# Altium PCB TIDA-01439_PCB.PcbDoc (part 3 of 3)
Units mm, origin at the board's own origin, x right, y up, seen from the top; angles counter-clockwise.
Board outline 105.8 x 40.5 mm, 4 copper layers (Layer 1 - Top Layer, Layer 2 - GND, Layer 3 - POWER, Layer 4 - Bottom Layer), stack 1.56 mm thick; 145 components, 123 nets, 523 pads, 227 vias.
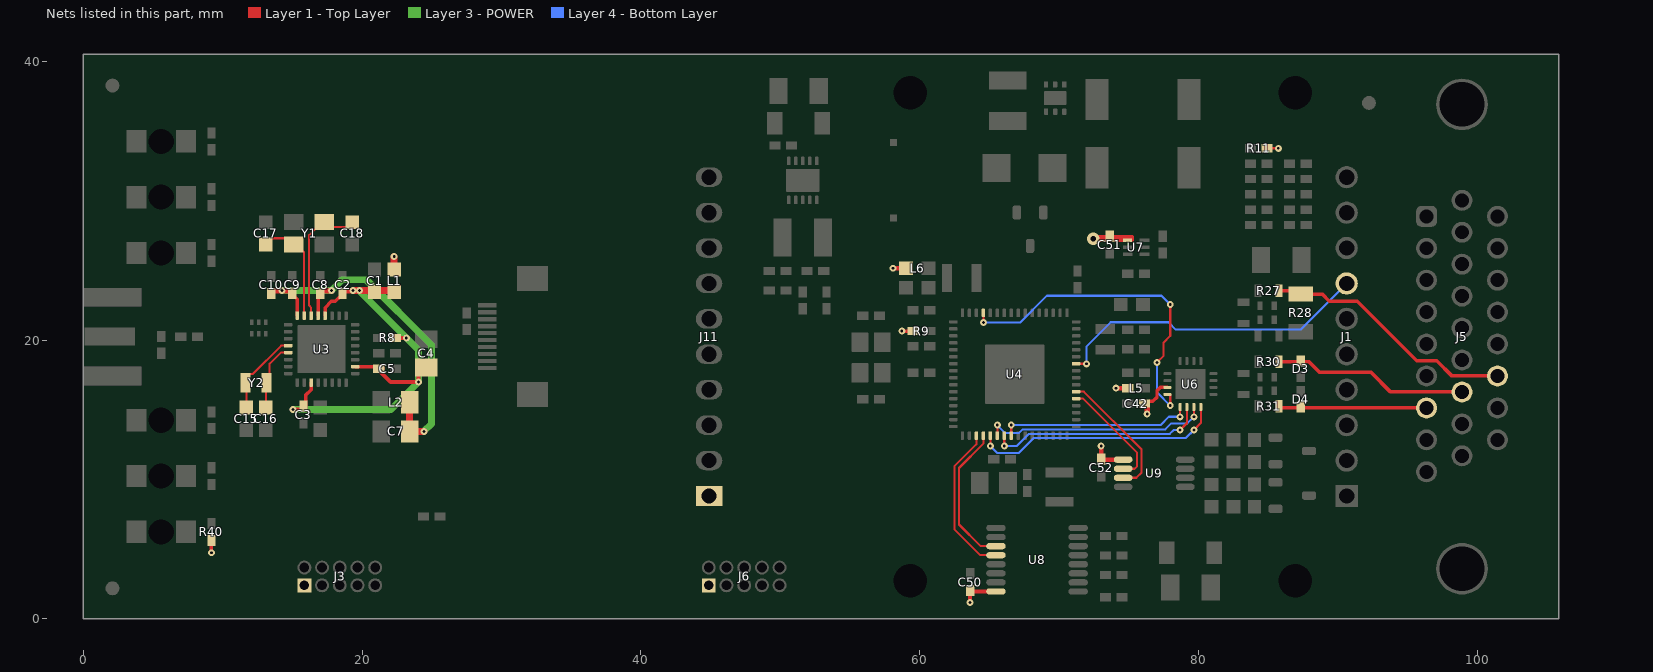
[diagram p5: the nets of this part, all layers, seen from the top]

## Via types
v1: diameter 0.5, hole 0.2, Layer 1 - Top Layer to Layer 4 - Bottom Layer, 215 vias
v2: diameter 0.9, hole 0.4, Layer 1 - Top Layer to Layer 4 - Bottom Layer, 12 vias

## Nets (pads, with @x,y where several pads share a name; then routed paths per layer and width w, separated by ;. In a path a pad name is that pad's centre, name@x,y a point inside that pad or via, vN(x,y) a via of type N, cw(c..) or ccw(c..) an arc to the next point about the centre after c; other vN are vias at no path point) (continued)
RTD1: J5.24 R27.1 R28.2 | length 18.7
  Layer 1 - Top Layer w0.25: R27.1@85.762,23.55 R28.2@87.9,23.55 ; R28.2@87.3,23.3 88.85,23.3 89.36,22.79 91.37,22.79 95.635,18.525 97.05,18.525 98.15,17.425 J5.24@101.41,17.425
RTD2: D3.1 J5.16 R30.1 | length 14
  Layer 1 - Top Layer w0.25: R30.1@85.762,18.45 87.9,18.45 88.64,17.71 92.315,17.71 93.745,16.28 J5.16@98.87,16.28
RTD3: D4.1 J5.7 R31.1 | length 10.6
  Layer 1 - Top Layer w0.25: R31.1@85.762,15.25 85.877,15.135 J5.7@96.33,15.135
RTD_CLK: U4.6 U6.15 | length 16.3
  Layer 1 - Top Layer w0.15: U4.6@65.55,13.15 v1(65.55,13.9) ; v1(79.65,14.5) U6.15@79.65,15.2
  Layer 4 - Bottom Layer w0.15: v1(65.55,13.9) 66.125,13.325 67.1,13.325 67.375,13.6 77.6,13.6 78.025,14.025 79.175,14.025 v1(79.65,14.5)
RTD_DRDY: U4.45 U6.12 | length 24.2
  Layer 1 - Top Layer w0.15: v1(64.55,21.25) U4.45@64.55,21.95 ; v1(77,18.4) 77.475,18.875 77.475,19.825 77.95,20.3 v1(77.95,22.55) ; U6.12@77.75,16.1 77.95,16.1 v1(77.95,15.3)
  Layer 4 - Bottom Layer w0.15: v1(64.55,21.25) 67.175,21.25 69.1,23.175 77.325,23.175 v1(77.95,22.55) ; v1(77,18.4) 77,16.25 v1(77.95,15.3)
RTD_NCS: U4.5 U6.16 | length 18.1
  Layer 1 - Top Layer w0.15: v1(65.05,12.4) U4.5@65.05,13.15 ; v1(79.65,13.55) 80.15,14.05 U6.16@80.15,15.2
  Layer 4 - Bottom Layer w0.15: v1(65.05,12.4) 65.55,11.9 67.075,11.9 68.15,12.975 79.075,12.975 v1(79.65,13.55)
RTD_SIMO: U4.7 U6.14 | length 15.7
  Layer 1 - Top Layer w0.15: v1(66.05,12.4) U4.7@66.05,13.15 ; v1(78.65,13.55) 79.15,14.05 U6.14@79.15,15.2
  Layer 4 - Bottom Layer w0.15: v1(66.05,12.4) 66.95,12.4 67.825,13.275 77.925,13.275 78.2,13.55 v1(78.65,13.55)
RTD_SOMI: U4.8 U6.13 | length 13.8
  Layer 1 - Top Layer w0.15: U4.8@66.55,13.15 v1(66.55,13.9) ; v1(78.65,14.5) U6.13@78.65,15.2
  Layer 4 - Bottom Layer w0.15: v1(66.55,13.9) 77.25,13.9 77.85,14.5 v1(78.65,14.5)
SOMI: J1.7 U4.26 | length 23
  Layer 1 - Top Layer w0.15: U4.26@71.2,18.3 v1(71.95,18.3)
  Layer 4 - Bottom Layer w0.15: v1(71.95,18.3) 71.95,19.55 73.675,21.275 77.825,21.275 78.35,20.75 87.29,20.75 J1.7@90.6,24.06
UART_A0_RX: U4.3 U8.12 | length 11.3
  Layer 1 - Top Layer w0.15: U4.3@64.05,13.15 64.05,12.525 62.475,10.95 62.475,6.425 64.325,4.575 U8.12@65.45,4.575 U8.12@65.65,4.575
UART_A0_TX: U4.4 U8.11 | length 10.6
  Layer 1 - Top Layer w0.15: U4.4@64.55,13.15 64.55,12.575 62.8,10.825 62.8,6.775 64.35,5.225 U8.11@65.45,5.225 U8.11@65.65,5.225
UART_A2_RX: U4.21 U9.2 | length 8
  Layer 1 - Top Layer w0.15: U4.21@71.2,15.8 71.7,15.8 75.575,11.925 75.575,10.95 75.4,10.775 U9.2@74.575,10.775
UART_A2_TX: U4.22 U9.3 | length 9.5
  Layer 1 - Top Layer w0.15: U4.22@71.2,16.3 71.75,16.3 75.9,12.15 75.9,10.5 75.525,10.125 U9.3@74.575,10.125
VCC: C42.1 C50.1 C51.1 C52.1 J3.1 J6.1 J11.1 L1.2 L5.1 L6.2 R9.2 R11.2 R40.1 U6.11 U7.1 U8.16 U9.1 | length 18.8
  Layer 1 - Top Layer w0.2: R11.2@84.9,33.75 v1(85.7,33.75)
  Layer 1 - Top Layer w0.25: v1(9.2,4.75) R40.1@9.2,5.65 ; v1(58.7,20.65) R9.2@59.525,20.65 ; C51.1@73.6,27.4 73.65,27.4 75.225,27.4 75.225,27.15 U7.1@74.88,27.15 ; C42.1@76.3,15.425 76.475,15.6 76.7,15.6 77,15.9 77,16.375 77.225,16.6 U6.11@77.75,16.6
  Layer 1 - Top Layer w0.3: v1(58.075,25.15) L6.2@59,25.15 ; v1(63.6,1.175) C50.1@63.6,1.975 ; C50.1@63.6,2.05 C50.1@63.6,1.975 ; U8.16@65.45,1.975 C50.1@63.6,1.975 ; C52.1@73,11.225 C52.1@73,11.425 ; v1(73,12.4) C52.1@73,11.45 C52.1@73,11.425 ; v1(74.05,16.55) L5.1@74.9,16.55 ; U9.1@74.575,11.425 C52.1@73,11.425
  Layer 1 - Top Layer w0.4: v1(76.3,14.7) C42.1@76.3,15.425
  Layer 1 - Top Layer w0.5: L1.2@22.3,25.05 v1(22.3,26) ; v2(72.425,27.275) C51.1@73.775,27.275 ; C51.1@73.6,27.45 73.65,27.4 C51.1@73.775,27.275 ; 75.1,27.275 74.9,27.275 C51.1@73.775,27.275
VDDR: C7.1 C8.1 C9.1 C10.1 L2.2 U3.29 U3.32 | length 29.1
  Layer 1 - Top Layer w0.25: C10.1@13.5,23.35 C10.1@13.5,23.6 ; C9.1@14.825,23.15 15.125,23.15 15.35,22.925 U3.32@15.35,21.75 ; C9.1@15,23.35 15,23.55 C9.1@15,23.6 ; U3.29@16.85,21.75 C8.1@16.85,23.6
  Layer 1 - Top Layer w0.4: C10.1@13.5,23.55 v1(14.25,23.55) C9.1@15,23.55 ; C8.1@16.9,23.55 v1(17.8,23.55)
  Layer 1 - Top Layer w0.5: C7.1@23.416,13.75 23.716,13.45 v1(24.45,13.45) ; C7.1@23.416,13.85 L2.2@23.416,15.85
  Layer 3 - POWER w0.5: v1(14.25,23.55) v1(17.8,23.55) 18.575,24.325 20.3,24.325 24.975,19.65 24.975,13.995 24.45,13.47 v1(24.45,13.45)
VDDS: C1.1 C2.1 C3.1 C4.1 C5.1 L1.1 R8.2 U3.11 U3.18 U3.28 | length 35.6
  Layer 1 - Top Layer w0.254: v1(15.05,15.025) 15.975,15.025 15.975,16.075 16.35,16.45 U3.11@16.35,16.95 ; U3.28@17.35,21.75 17.35,22.325 17.8,22.775 18.075,22.775 C2.1@18.425,23.125 ; U3.18@19.5,18.1 21.475,18.1 21.475,17.575
  Layer 1 - Top Layer w0.3: C5.1@21.2,17.95 21.2,17.85 21.475,17.575 22.05,17 v1(24.05,17) 24.05,17.684 C4.1@24.6,18.234 ; R8.2@22.4,20.15 v1(23.175,20.15)
  Layer 1 - Top Layer w0.4: C2.1@18.625,23.55 v1@19.375,23.55
  Layer 1 - Top Layer w0.5: v1@19.375,23.55 22.3,23.55 L1.1@22.3,23.45 ; C4.1@24.6,18.234 C4.1@24.766,18.4
  Layer 3 - POWER w0.5: v1(15.05,15.025) 22.075,15.025 v1(24.05,17) 24.05,19.275 v1(23.175,20.15) 19.775,23.55 v1@19.375,23.55
  other v1: 19.35,23.55 19.825,23.55
X24M_N: C18.1 U3.30 Y1.1 | length 9.3
  Layer 1 - Top Layer w0.15: U3.30@16.35,21.75 16.35,22.325 16.2,22.475 16.2,27.525 16.775,28.1 C18.1@19.375,28.1
X24M_P: C17.1 U3.31 Y1.3 | length 7.8
  Layer 1 - Top Layer w0.15: C17.1@13.2,26.9 13.6,27.3 14.825,27.3 15.85,26.275 U3.31@15.85,21.75
X32K_Q1: C15.2 U3.4 Y2.1 | length 6.3
  Layer 1 - Top Layer w0.15: C15.2@11.7,15.15 11.7,17.575 12.175,17.575 14.2,19.6 U3.4@14.7,19.6
X32K_Q2: C16.1 U3.5 Y2.2 | length 5.1
  Layer 1 - Top Layer w0.15: C16.1@13.1,15.15 13.1,16.975 13.375,16.975 13.375,18.3 14.175,19.1 U3.5@14.7,19.1
pads on no net: D1.0 D2.0 D8.0 D9.0 D10.0 D13.0 FID1.1 FID2.1 FID3.1 J3.6 J3.7 J3.8 J4.M1 J4.M2 J5.6 J5.15 J5.23 J6.6 J6.7 J6.8 U1.7@69.25,37.35 U1.7@70.15,37.35 U3. U3.3 U3.6 U3.7 U3.10 U3.15 U3.20 U3.21 U3.22 U3.27 U4.37 U4.46 U4.61 U4.62 U4.65@65.41,16.16 U4.65@65.41,17.55 U4.65@65.41,18.94 U4.65@66.8,16.16 U4.65@66.8,17.55 U4.65@66.8,18.94 U4.65@68.19,16.16 U4.65@68.19,17.55 U4.65@68.19,18.94 U5.6 U7.5 U8.7 U8.8 U8.9 U8.10

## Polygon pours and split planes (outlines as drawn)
GND on Layer 2 - GND "LAYER_2_-_GND_GND_P000" (solid, remove dead copper, pour order 0): 0.5,0.5 0.5,40 3.35,40 105.3,40 105.3,0.5
GND on Layer 1 - Top Layer "PolyDirectConnect" (solid, remove dead copper, pour order 4): 67.3,13.75 63.2,13.75 63,13.95 63,21.15 63.2,21.35 70.4,21.35 70.6,21.15 70.6,13.95 70.4,13.75
GND on Layer 1 - Top Layer "PolyDirectConnect" (solid, remove dead copper, pour order 8): 4.125,23.75 12.55,23.75 12.7,23.6 12.7,19.125 11.825,18.25 10.95,18.25 9.45,16.75 4.05,16.75 4.05,23.75
VCC on Layer 3 - POWER "LAYER_3_-_POWER_VCC_P002" (solid, remove dead copper, pour order 2): 1.6,1.25 1.6,34 1.6,38.9 48.1,38.9 53,34 95.25,34 98.1,31.15 98.1,21.75 98.6,21.25 104.55,21.25 104.55,1.25 95.25,1.25

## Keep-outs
Layer 1 - Top Layer:
  circle w0.1: c59.3,2.75 r2.5
  circle w0.1: c86.9,2.75 r2.5
  circle w0.1: c86.9,37.75 r2.5
  circle w0.1: c59.3,37.75 r2.5
Layer 2 - GND:
  lines w0.05: 11.8,12.325 13.75,12.325 14.05,12.625 14.05,18.375 14.4,18.725 14.95,18.725 ; 11.825,12.325 11.05,12.325 10.75,12.625 10.75,17.75 11.05,18.05 11.925,18.05 12.025,18.15 13.875,20 14.95,20 ; 15.45,22.05 15.45,25.5 15.075,25.875 12.35,25.875 12.15,26.075 12.15,29.175 12.4,29.425 20,29.425 20.25,29.175 20.25,26.2 19.925,25.875 16.925,25.875 16.55,25.5 16.55,22.05 ; 61.225,19.025 61.15,19.1 58.5,19.1 58.25,19.35 58.25,22.275 58,22.525 54.8,22.525 54.55,22.275 54.55,15.3 54.875,14.975 57.925,14.975 58.25,15.3 58.25,17.85 58.5,18.1 61.825,18.1 61.875,18.05 62.6,18.05 ; 70.875,20.3 71.725,20.3 72.95,21.525 77.45,21.525 77.45,18.875 76.8,18.875 76.5,18.575 73.35,18.575 73.125,18.8 70.9,18.8
Layer 4 - Bottom Layer:
  circle w0.1: c59.3,37.75 r2.5
  circle w0.1: c86.9,37.75 r2.5
  circle w0.1: c86.9,2.75 r2.5
  circle w0.1: c59.3,2.75 r2.5
Keep-Out Layer:
  lines w0.7: -0.5,16.35 -0.5,24.15 0,24.65 0,40.5 105.8,40.5 105.8,0 0,0 0,15.85 -0.5,16.35 ; 38.9,15.25 ccw(c39.9,15.25) 39.9,14.25 40.9,14.25 ccw(c40.9,15.25) 41.9,15.25 41.9,25.25 ccw(c40.9,25.25) 40.9,26.25 39.9,26.25 ccw(c39.9,25.25) 38.9,25.25 38.9,20.25 38.9,15.25
  text ".Layer_Name" at -13.844,-39.756 h1.52

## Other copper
Layer 1 - Top Layer:
  rectangle: 29.65,8.1 35.3,13.75
  region net GND: 49.7,23.15 49.7,25.5 50.1,25.9 50.9,25.9 50.9,28.85 50.225,29.525 50.225,30.475 50.375,30.625 53.725,30.625 53.725,32.275 50.15,32.275 50,32.425 50,34.25 50.6,34.85 50.6,38.875 47.6,38.875 47.6,23.15
  region net NetC26_1: 51.975,32.55 51.975,33.275 51.75,33.5 51.75,38.875 53.65,38.875 53.65,36.375 53.65,34.675 52.225,33.25 52.225,32.55
  region net NetL7_1: 52.475,32.55 52.475,33.125 54.375,35.025 61.05,35.025 61.25,34.825 61.25,33.9 56.113,33.9 56.113,32.4 54.95,32.4 54.8,32.55
  region net NetC27_1: 52.3,25.9 52.3,28.8 54.6,28.8 54.975,29.175 61.25,29.175 61.25,27.45 61.05,27.25 53.8,27.25 53.8,26.8 54.5,26.8 54.5,25.9
  region net NetFL1_1: 12.205,20.665 11.65,20.665 11.65,20.25 12.205,20.25
  region net GND: 68.9,37.675 68.9,36.1 68.8,36 65.225,36 65.225,35.15 70,35.15 70.5,35.65 70.5,37.675
  text ".Layer_Name" at -13.844,-39.756 h1.52
Layer 4 - Bottom Layer:
  text "GCD_13112" at 8.2,0.9 h0.9
  text ".Layer_Name" at -13.844,-39.756 h1.52

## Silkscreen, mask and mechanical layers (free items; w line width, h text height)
Top Overlay:
  region: 46.12,39.54 38.5,39.54 38.5,37 46.12,37
  lines w0.1: 61.3,19.55 61.6,19.55 61.7,19.65 61.7,21.15 ; 61.3,21.15 61.7,21.15 ; 61.3,22.15 61.7,22.15 ; 65.3,24.35 65.7,24.35 ; 65.7,23.45 65.3,23.45 ; 65.7,25.25 65.3,25.25 65.3,23.45 ; 79,8.55 79.409,8.959 80.176,8.959 ; 79,12.35 79.407,11.943 80.176,11.943 ; 82.1,21.95 82.8,21.95 ; 85.8,16.55 86.1,16.85 ; 85.8,17.15 86.1,16.85 ; 88.3,28.25 88.9,28.25 89.3,27.85 91.5,27.85 ; 88.3,29.35 88.8,29.35 89.6,30.15 91.5,30.15 ; 88.3,31.55 88.8,31.55 90,32.75 91.5,32.75 ; 88.3,32.65 88.9,32.65 89.7,33.45 91.5,33.45 ; 88.4,30.45 91.1,30.45 91.5,30.85 ; 91.6,17.35 91.3,17.65 ; 91.6,17.95 91.3,17.65 ; 61.7,21.15 61.7,22.45 61.9,22.65 64.5,22.65 65.3,23.45 ; 86.1,16.85 89.2,16.85 90,17.65 91.3,17.65
  text "'.PRJ_Number' .PCB_Rev" at 17.1,37.5 h1.5
  text "-" at 36.4,37.5 h1.5
  text ".Layer_Name" at -13.844,-39.756 h1.52
Bottom Overlay:
  text ".Layer_Name" at -13.844,-39.756 h1.52
Top Paste:
  text ".Layer_Name" at -13.844,-39.756 h1.52
Bottom Paste:
  text ".Layer_Name" at -13.844,-39.756 h1.52
Top Solder:
  lines w0.2: 0,0 105.8,0 105.8,40.5 0,40.5 0,0 ; 38.9,15.25 ccw(c39.9,15.25) 39.9,14.25 40.9,14.25 ccw(c40.9,15.25) 41.9,15.25 41.9,25.25 ccw(c40.9,25.25) 40.9,26.25 39.9,26.25 ccw(c39.9,25.25) 38.9,25.25 38.9,20.25 38.9,15.25
  text ".Layer_Name" at -13.844,-39.756 h1.52
  text ".Layer_Name" at -13.844,-39.756 h1.52
Bottom Solder:
  lines w0.2: 0,0 105.8,0 105.8,40.5 0,40.5 0,0 ; 38.9,15.25 ccw(c39.9,15.25) 39.9,14.25 40.9,14.25 ccw(c40.9,15.25) 41.9,15.25 41.9,25.25 ccw(c40.9,25.25) 40.9,26.25 39.9,26.25 ccw(c39.9,25.25) 38.9,25.25 38.9,20.25 38.9,15.25
  text ".Layer_Name" at -13.844,-39.756 h1.52
Drill Guide:
  text ".Layer_Name" at -13.844,-39.756 h1.52
M1 Board Outline:
  lines w0.2: 0,0 0,40.5 105.8,40.5 105.8,0 0,0 ; 38.9,15.25 ccw(c39.9,15.25) 39.9,14.25 40.9,14.25 ccw(c40.9,15.25) 41.9,15.25 41.9,25.25 ccw(c40.9,25.25) 40.9,26.25 39.9,26.25 ccw(c39.9,25.25) 38.9,25.25 38.9,20.25 38.9,15.25
  text ".Layer_Name" at -13.844,-39.756 h1.52
M2 Board Dimensions:
  rectangle: 0,-13.175 3.175,-10
  rectangle: 3.175,-16.35 12.7,-13.175
  lines w0.178: 0,-13.175 25.4,-13.175 ; 3.175,-16.35 3.175,-10 ; 6.35,-16.35 6.35,-10 ; 12.7,-16.35 12.7,-10 ; 19.05,-16.35 19.05,-10 ; 0,-16.35 25.4,-16.35 25.4,-10 0,-10 0,-16.35
  lines w0.2: 0,0 105.8,0 105.8,40.5 0,40.5 0,0 ; 38.9,15.25 ccw(c39.9,15.25) 39.9,14.25 40.9,14.25 ccw(c40.9,15.25) 41.9,15.25 41.9,25.25 ccw(c40.9,25.25) 40.9,26.25 39.9,26.25 ccw(c39.9,25.25) 38.9,25.25 38.9,20.25 38.9,15.25
  text ".Layer_Name" at -13.844,-39.756 h1.52
M3 3D STEP Top:
  text ".Layer_Name" at -13.844,-39.756 h1.52
M4 3D STEP Bottom:
  text ".Layer_Name" at -13.844,-39.756 h1.52
M5 Assembly Top:
  lines w0.254: -35.917,-41.576 131.723,-41.576 ; -35.917,-36.412 131.774,-36.412 ; -35.917,-31.247 -35.917,-46.741 65.81,-46.741 131.774,-46.741 131.774,-31.247 -35.904,-31.247 -35.904,-46.741 4.114,-46.741 ; 26.694,-46.741 26.694,-31.247 ; 58.876,-36.412 58.876,-31.247 ; 80.212,-36.412 80.212,-31.247 ; 96.011,-46.906 96.011,-41.754
  text "COMPONENTS MARKED 'DNP' SHOULD NOT BE POPULATED." at 126.524,-23.265 h1.52
  text "ASSEMBLY VARIANT:" at 126.511,-26.199 h1.52
  text ".VariantName" at 152.826,-26.199 h1.52
  text "PCB VIEWED FROM TOP SIDE" at -34.304,-34.604 h1.52
  text "BOARD #:" at 28.599,-34.604 h1.52
  text ".PRJ_Number" at 42.455,-34.604 h1.52
  text "REV:" at 63.905,-34.604 h1.52
  text ".PCB_Rev" at 71.309,-34.604 h1.52
  text "SVN REV:" at 85.19,-34.604 h1.52
  text ".VersionControl_RevNumber" at 98.043,-34.604 h1.52
  text "TID #:" at 28.599,-39.769 h1.52
  text ".TID" at 42.455,-39.769 h1.52
  text "PLOT NAME =" at -34.304,-44.984 h1.52
  text ".plot_File_Name" at -13.844,-44.984 h1.52
  text "GENERATED    :" at 28.65,-44.984 h1.52
  text ".Print_Date" at 50.735,-44.984 h1.52
  text ".Print_Time" at 69.252,-44.984 h1.52
  text "TEXAS INSTRUMENTS" at 101.37,-44.984 h1.52
M6 Assembly Bottom:
  lines w0.254: -35.929,-36.424 131.761,-36.424 ; -35.879,-41.589 131.761,-41.589 ; -0.166,-46.919 -0.166,-41.767 ; 15.633,-36.424 15.633,-31.26 ; 36.969,-36.424 36.969,-31.26 ; 69.15,-46.754 69.15,-31.26 ; 91.731,-46.754 131.749,-46.754 131.749,-31.26 -35.929,-31.26 -35.929,-46.754 30.034,-46.754 131.761,-46.754 131.761,-31.26
  text "COMPONENTS MARKED 'DNP' SHOULD NOT BE POPULATED." at 252.216,-23.252 h1.52
  text ".VariantName" at 225.698,-26.199 h1.52
  text "ASSEMBLY VARIANT:" at 252.089,-26.199 h1.52
  text ".VersionControl_RevNumber" at -2.198,-34.617 h1.52
  text "SVN REV:" at 10.654,-34.617 h1.52
  text ".PCB_Rev" at 24.535,-34.617 h1.52
  text "REV:" at 31.939,-34.617 h1.52
  text ".PRJ_Number" at 53.39,-34.617 h1.52
  text "BOARD #:" at 67.245,-34.617 h1.52
  text "PCB VIEWED FROM BOTTOM SIDE" at 130.148,-34.617 h1.52
  text ".TID" at 53.39,-39.781 h1.52
  text "TID #:" at 67.245,-39.781 h1.52
  text "TEXAS INSTRUMENTS" at -5.526,-44.997 h1.52
  text ".Print_Time" at 26.593,-44.997 h1.52
  text ".Print_Date" at 45.109,-44.997 h1.52
  text "GENERATED    :" at 67.195,-44.997 h1.52
  text ".plot_File_Name" at 109.689,-44.997 h1.52
  text "PLOT NAME =" at 130.148,-44.997 h1.52
M9 Title Sheet:
  drawing of 57 lines, arcs and shapes, not listed
  text "1" at -9.708,186.177 h1.78
  text "2" at 53.682,186.177 h1.78
  text "3" at 116.911,186.177 h1.78
  text "4" at 180.58,186.177 h1.78
  text "5" at 244.055,186.177 h1.78
  text "6" at 307.682,186.177 h1.78
  text "A" at -39.079,157.145 h1.78
  text "A" at 336.841,157.145 h1.78
  text "B" at -39.079,96.693 h1.78
  text "B" at 336.841,96.693 h1.78
  text "C" at -39.079,36.368 h1.78
  text "C" at 336.841,36.368 h1.78
  text "PROJECT TITLE:" at 259.625,-10.901 h1.14
  text ".PRJ_Title" at 260.895,-14.288 h1.78
  text "DESIGNED FOR:" at 259.625,-18.547 h1.14
  text ".PRJ_Customer" at 260.895,-22.103 h1.78
  text "D" at -39.079,-23.83 h1.78
  text "D" at 336.841,-23.83 h1.78
  text "FILE NAME:" at 259.625,-26.167 h1.14
  text ".PCB_File_Name_No_Path" at 260.895,-29.215 h1.78
  text "Texas Instruments (TI) and/or its licensors do not warrant the accuracy or completeness of this specification" at 133.4,-33.326 h1.14
  text "ENGINEER:" at 259.625,-33.533 h1.14
  text "LAYOUT BY:" at 297.852,-33.533 h1.14
  text "or any information contained therein. TI and/or its licensors do not warrant that this design will meet" at 132.257,-36.187 h1.14
  text ".PRJ_Engineer" at 260.895,-37.47 h1.78
  text ".PCB_Layout" at 299.135,-37.47 h1.78
  text "the specifications, will be suitable for your application or fit for any particular purpose, or will operate in" at 132.257,-39.049 h1.14
  text ".Layer_Name" at -13.844,-39.756 h1.52
  text "ALTIUM DESIGNER VERSION:" at 297.852,-41.407 h1.14
  text "an implementation. TI and/or its licensors do not warrant that the design is production worthy. You should" at 132.257,-41.911 h1.14
  text "completely validate and test your design implementation to confirm the system functionality for your application." at 133.4,-44.772 h1.14
  text ".print_Scale" at 260.895,-44.793 h1.78
  text ".Application_BuildNumber" at 299.135,-44.793 h1.78
  text "1" at -9.708,-50.043 h1.78
  text "2" at 53.682,-50.043 h1.78
  text "3" at 116.911,-50.043 h1.78
  text "4" at 180.58,-50.043 h1.78
  text "5" at 244.055,-50.043 h1.78
  text "6" at 307.682,-50.043 h1.78
M10 Fab Notes:
  drawing of 173 lines, arcs and shapes, not listed
  text "DESIGN INFORMATION" at 285.902,139.555 h1.52
  text "MIN. TRACK WIDTH:" at 269.53,134.983 h1.52
  text "8" at 297.374,134.983 h1.52
  text "MIL" at 301.305,134.983 h1.52
  text "MIN. CLEARANCE:" at 269.53,131.631 h1.52
  text "0.2" at 295.85,131.631 h1.52
  text "mm" at 301.305,131.631 h1.52
  text "MIN. VIA PAD SIZE:" at 269.53,128.278 h1.52
  text "24" at 296.613,128.278 h1.52
  text "MIL" at 301.305,128.278 h1.52
  text "0.05mm (2MIL)" at 287.183,124.678 h1.52
  text "MINIMUM ANNULAR RING" at 261.167,124.57 h1.52
  text "EXTERNAL" at 305.166,124.57 h1.52
  text "PER" at 266.247,121.572 h1.52
  text "IPC-D-275 CLASS 2 LEVEL C" at 271.835,121.572 h1.52
  text "MIL, HOLES" at 309.636,118.72 h1.52
  text "+/-" at 299.668,118.702 h1.52
  text "+/-" at 321.36,118.702 h1.52
  text "REGISTRATION TOLERANCES:" at 261.167,118.575 h1.52
  text "METAL" at 291.642,118.575 h1.52
  text "5" at 306.277,118.575 h1.52
  text "3" at 327.435,118.575 h1.52
  text "MIL" at 330.388,118.575 h1.52
  text "+/-" at 321.36,115.705 h1.52
  text "HOLE SIZE TOLERANCE (UNLESS OTHERWISE SPECIFIED):" at 261.167,115.578 h1.52
  text "3" at 327.435,115.578 h1.52
  text "MIL" at 330.388,115.578 h1.52
  text "MATERIAL:" at 259.268,110.258 h1.52
  text "FR-4 High Tg" at 284.324,106.693 h1.52
  text "FR-408" at 269.962,106.475 h1.52
  text "OTHER" at 307.757,106.475 h1.52
  text "X" at 280.389,106.383 h1.52
  text "62 MIL (1.6mm) +/-10%" at 278.092,102.342 h1.52
  text "THICKNESS:" at 261.167,102.234 h1.52
  text "X" at 274.837,102.234 h1.52
  text "OTHER" at 310.729,102.234 h1.52
  text "TOLERANCE:" at 261.167,98.22 h1.52
  text "X" at 282.486,98.22 h1.52
  text "ANSI IPC-6012 TYPE 3 CLASS 2" at 287.234,98.22 h1.52
  text "OTHER +/-" at 287.234,94.258 h1.52
  text "BOW & TWIST:" at 261.167,90.27 h1.52
  text "X" at 282.486,90.27 h1.52
  text "ANSI IPC-6012 TYPE 3 CLASS 2" at 287.234,90.27 h1.52
  text "OTHER +/-" at 287.234,86.244 h1.52
  text "DRILLING:" at 259.268,82.726 h1.52
  text "REFERENCE:" at 261.167,79.755 h1.52
  text "X" at 277.632,79.755 h1.52
  text "AS SHOWN" at 282.382,79.755 h1.52
  text "X" at 300.518,79.755 h1.52
  text "NC_DRILL FILES" at 303.998,79.755 h1.52
  text "PTH COPPER THICKNESS:" at 261.167,75.741 h1.52
  text "X" at 289.875,75.741 h1.52
  text "20-30 um" at 293.355,75.741 h1.52
  text "OTHER" at 311.567,75.741 h1.52
  text "BOARD FINISH:" at 259.268,71.703 h1.52
  text "SILKSCREEN:" at 263.211,68.706 h1.52
  text "X" at 287.31,68.706 h1.52
  text "TOP" at 290.51,68.706 h1.52
  text "BOTTOM" at 303.49,68.706 h1.52
  text "SILKSCREEN COLOR:" at 263.211,64.464 h1.52
  text "X" at 287.283,64.464 h1.52
  text "WHITE" at 290.51,64.464 h1.52
  text "OTHER" at 303.49,64.464 h1.52
  text "X" at 290.611,60.42 h1.52
  text "GREEN" at 293.838,60.42 h1.52
  text "OTHER" at 309.535,60.42 h1.52
  text "SOLDER RESIST COLOR:" at 263.211,60.146 h1.52
  text "X" at 290.611,56.102 h1.52
  text "MATTE" at 293.838,56.102 h1.52
  text "SEMI-GLOSS" at 309.523,56.086 h1.52
  text "IMMERSION GOLD (ENIG)" at 286.218,51.314 h1.52
  text "ENEPIG" at 320.191,51.23 h1.52
  text "SURFACE FINISH:" at 259.268,51.205 h1.52
  text "X" at 281.469,51.205 h1.52
  text "IMM. TIN/SILVER OR EQUIV" at 267.639,47.217 h1.52
  text "OTHER" at 303.998,47.217 h1.52
  text "ARRAY/PANEL:" at 259.268,42.671 h1.52
  text "CUT AND TRIM PER M1 BOARD OUTLINE" at 286.218,42.562 h1.52
  text "N.C. ROUTE" at 286.218,38.708 h1.52
  text "X" at 303.464,38.708 h1.52
  text "V. SCORE" at 308.214,38.708 h1.52
  text "CERTIFICATION:" at 259.268,35.228 h1.52
  text "MATERIALS AND WORKMANSHIP FOR ALL PCBS" at 277.683,35.228 h1.52
  text "TO MEET OR EXCEED THE REQUIREMENTS OF:" at 277.683,32.739 h1.52
  text "X" at 268.196,29.272 h1.52
  text "ANSI IPC-A-600F CLASS ->" at 271.727,29.272 h1.52
  text "X" at 313.359,29.272 h1.52
  text "2" at 316.38,29.272 h1.52
  text "1" at 308.379,29.234 h1.52
  text "3" at 325.372,29.234 h1.52
  text "X" at 288.873,25.221 h1.52
  text "RoHS" at 292.352,25.221 h1.52
  text "OTHER" at 308.72,25.221 h1.52
  text "PER ORDER" at 318.805,25.221 h1.52
  text "ALL BOARDS MUST MEET OR EXCEED UL94-V0 REQUIREMENTS." at 259.968,21.014 h1.52
  text "PCB MUST BEAR THE UL94V-0 UL REGISTERED MATERIAL ID NUMBER" at 259.968,17.966 h1.52
  text "ADDITIONAL REQUIREMENTS:" at 259.268,13.562 h1.52
  text "MICROSECTION:" at 261.167,10.641 h1.52
  text "YES" at 284.173,10.641 h1.52
  text "REQUIRED" at 306.055,6.675 h1.52
  text "BARE BOARD ELEC. TEST:" at 261.167,6.603 h1.52
  text "NONE" at 294.333,6.603 h1.52
  text "X" at 302.829,6.603 h1.52
  text "PER ORDER" at 321.092,6.603 h1.52
  text ".Layer_Name" at -13.844,-39.756 h1.52
M11 Gerber Information:
  lines w0.254: -35.917,-41.576 131.723,-41.576 ; -35.917,-36.412 131.774,-36.412 ; -35.917,-31.247 -35.917,-46.741 65.81,-46.741 131.774,-46.741 131.774,-31.247 -35.904,-31.247 -35.904,-46.741 4.114,-46.741 ; 26.694,-46.741 26.694,-31.247 ; 58.876,-36.412 58.876,-31.247 ; 80.212,-36.412 80.212,-31.247 ; 96.011,-46.906 96.011,-41.754
  text "ALL ARTWORK VIEWED FROM TOP SIDE" at -34.304,-34.604 h1.52
  text "BOARD #:" at 28.599,-34.604 h1.52
  text ".PRJ_Number" at 42.455,-34.604 h1.52
  text "REV:" at 63.905,-34.604 h1.52
  text ".PCB_Rev" at 71.309,-34.604 h1.52
  text "SVN REV:" at 85.19,-34.604 h1.52
  text ".VersionControl_RevNumber" at 98.043,-34.604 h1.52
  text "LAYER NAME =" at -34.304,-39.756 h1.52
  text "TID #:" at 28.599,-39.769 h1.52
  text ".TID" at 42.455,-39.769 h1.52
  text "PLOT NAME =" at -34.304,-44.984 h1.52
  text ".plot_File_Name" at -13.844,-44.984 h1.52
  text "GENERATED    :" at 28.65,-44.984 h1.52
  text ".Print_Date" at 50.735,-44.984 h1.52
  text ".Print_Time" at 69.252,-44.984 h1.52
  text "TEXAS INSTRUMENTS" at 101.37,-44.984 h1.52
M12 Stackup:
  drawing of 295 lines, arcs and shapes, not listed
  text "Layer" at 127.109,36.527 h1.52
  text "Name" at 137.52,36.527 h1.52
  text "Material" at 173.324,36.527 h1.52
  text "Thickness" at 195.162,36.527 h1.52
  text "Constant" at 211.668,36.527 h1.52
  text "Board Layer Stack" at 226.142,36.527 h1.52
  text "1" at 127.109,33.479 h1.52
  text "Top Overlay" at 137.52,33.479 h1.52
  text "2" at 127.109,30.431 h1.52
  text "Top Solder" at 137.52,30.431 h1.52
  text "Solder Resist" at 173.324,30.431 h1.52
  text "0.40mil" at 195.162,30.431 h1.52
  text "3.5" at 211.668,30.431 h1.52
  text "3" at 127.109,27.383 h1.52
  text "Layer 1 - Top Layer" at 137.52,27.383 h1.52
  text "Copper" at 173.324,27.383 h1.52
  text "1.40mil" at 195.162,27.383 h1.52
  text "4" at 127.109,24.335 h1.52
  text "Dielectric1" at 137.52,24.335 h1.52
  text "370HR" at 173.324,24.335 h1.52
  text "18.60mil" at 195.162,24.335 h1.52
  text "4.2" at 211.668,24.335 h1.52
  text "5" at 127.109,21.287 h1.52
  text "Layer 2 - GND" at 137.52,21.287 h1.52
  text "Copper" at 173.324,21.287 h1.52
  text "1.40mil" at 195.162,21.287 h1.52
  text "6" at 127.109,18.239 h1.52
  text "Dielectric3" at 137.52,18.239 h1.52
  text "370HR" at 173.324,18.239 h1.52
  text "18.60mil" at 195.162,18.239 h1.52
  text "4.2" at 211.668,18.239 h1.52
  text "7" at 127.109,15.191 h1.52
  text "Layer 3 - POWER" at 137.52,15.191 h1.52
  text "Copper" at 173.324,15.191 h1.52
  text "1.40mil" at 195.162,15.191 h1.52
  text "8" at 127.109,12.143 h1.52
  text "Dielectric2" at 137.52,12.143 h1.52
  text "370HR" at 173.324,12.143 h1.52
  text "18.60mil" at 195.162,12.143 h1.52
  text "4.2" at 211.668,12.143 h1.52
  text "9" at 127.109,9.095 h1.52
  text "Layer 4 - Bottom Layer" at 137.52,9.095 h1.52
  text "Copper" at 173.324,9.095 h1.52
  text "1.40mil" at 195.162,9.095 h1.52
  text "10" at 127.109,6.047 h1.52
  text "Bottom Solder" at 137.52,6.047 h1.52
  text "Solder Resist" at 173.324,6.047 h1.52
  text "0.40mil" at 195.162,6.047 h1.52
  text "3.5" at 211.668,6.047 h1.52
  text "11" at 127.109,2.999 h1.52
  text "Bottom Overlay" at 137.52,2.999 h1.52
  text "FabNote: Impedance calculated trace (Z0=50R) on TopLayer,  trace width = 30mil" at 126.3,-2.5 h1.52
  text ".Layer_Name" at -13.844,-39.756 h1.52
M13 Component Bodies Top:
  text ".Layer_Name" at -13.844,-39.756 h1.52
M14 Component Bodies Bottom:
  text ".Layer_Name" at -13.844,-39.756 h1.52
M15 Courtyards Top:
  text ".Layer_Name" at -13.844,-39.756 h1.52
M16 Courtyards Bottom:
  text ".Layer_Name" at -13.844,-39.756 h1.52
Drill Drawing:
  circle w0.203: c143.79,57.34 r0.339
  circle w0.203: c143.79,57.34 r0.564
  circle w0.203: c143.79,54.8 r0.564
  lines w0.203: 143.226,59.316 143.226,59.598 143.508,59.88 143.226,60.162 143.226,60.445 143.508,60.445 143.79,60.162 144.072,60.445 144.355,60.445 144.355,60.162 144.072,59.88 144.355,59.598 144.355,59.316 144.072,59.316 143.79,59.598 143.508,59.316 143.226,59.316 ; 143.226,62.138 143.508,62.138 143.79,61.856 144.072,62.138 144.355,62.138 144.072,62.42 144.355,62.702 144.072,62.702 143.79,62.985 143.508,62.702 143.226,62.702 143.508,62.42 143.226,62.138 ; 143.226,64.396 144.355,64.396 144.355,65.525 143.226,65.525 143.226,64.396 ; 143.226,68.065 144.355,68.065 143.79,66.936 143.226,68.065 ; 143.226,69.476 144.355,69.476 144.355,70.605 143.226,70.605 143.226,69.476 ; 143.226,72.016 143.79,72.298 144.355,72.016 144.072,72.58 144.355,73.145 143.79,72.862 143.226,73.145 143.508,72.58 143.226,72.016 ; 143.451,69.701 144.129,69.701 144.129,70.379 143.451,70.379 143.451,69.701
  lines w0.254: 142.203,53.474 253.017,53.474 ; 142.203,73.794 253.017,73.794 ; 151.639,50.934 151.639,76.334 ; 162.548,50.934 162.548,76.334 ; 185.442,50.934 185.442,76.334 ; 194.117,50.934 194.117,76.334 ; 206.651,50.934 206.651,76.334 ; 142.203,50.934 253.017,50.934 253.017,76.334 142.203,76.334 142.203,50.934
  text "Symbol" at 143.727,74.556 h1.22
  text "Quantity" at 152.401,74.556 h1.22
  text "Finished Hole Size" at 163.31,74.556 h1.22
  text "Plated" at 186.204,74.556 h1.22
  text "Hole Type" at 194.879,74.556 h1.22
  text "Drill Layer Pair" at 207.413,74.556 h1.22
  text "215" at 152.401,72.016 h1.02
  text "0.200mm (7.87mil)" at 163.31,72.016 h1.02
  text "PTH" at 186.204,72.016 h1.02
  text "Round" at 194.879,72.016 h1.02
  text "Layer 1 - Top Layer - Layer 4 - Bottom Layer" at 207.413,72.016 h1.02
  text "12" at 152.401,69.476 h1.02
  text "0.400mm (15.75mil)" at 163.31,69.476 h1.02
  text "PTH" at 186.204,69.476 h1.02
  text "Round" at 194.879,69.476 h1.02
  text "Layer 1 - Top Layer - Layer 4 - Bottom Layer" at 207.413,69.476 h1.02
  text "20" at 152.401,66.936 h1.02
  text "0.700mm (27.56mil)" at 163.31,66.936 h1.02
  text "PTH" at 186.204,66.936 h1.02
  text "Round" at 194.879,66.936 h1.02
  text "Layer 1 - Top Layer - Layer 4 - Bottom Layer" at 207.413,66.936 h1.02
  text "26" at 152.401,64.396 h1.02
  text "1.000mm (39.37mil)" at 163.31,64.396 h1.02
  text "PTH" at 186.204,64.396 h1.02
  text "Round" at 194.879,64.396 h1.02
  text "Layer 1 - Top Layer - Layer 4 - Bottom Layer" at 207.413,64.396 h1.02
  text "20" at 152.401,61.856 h1.02
  text "1.100mm (43.31mil)" at 163.31,61.856 h1.02
  text "PTH" at 186.204,61.856 h1.02
  text "Round" at 194.879,61.856 h1.02
  text "Layer 1 - Top Layer - Layer 4 - Bottom Layer" at 207.413,61.856 h1.02
  text "6" at 152.401,59.316 h1.02
  text "1.800mm (70.87mil)" at 163.31,59.316 h1.02
  text "NPTH" at 186.204,59.316 h1.02
  text "Slot" at 194.879,59.316 h1.02
  text "Layer 1 - Top Layer - Layer 4 - Bottom Layer" at 207.413,59.316 h1.02
  text "4" at 152.401,56.776 h1.02
  text "2.400mm (94.49mil)" at 163.31,56.776 h1.02
  text "NPTH" at 186.204,56.776 h1.02
  text "Round" at 194.879,56.776 h1.02
  text "Layer 1 - Top Layer - Layer 4 - Bottom Layer" at 207.413,56.776 h1.02
  text "2" at 152.401,54.236 h1.02
  text "3.200mm (125.98mil)" at 163.31,54.236 h1.02
  text "PTH" at 186.204,54.236 h1.02
  text "Round" at 194.879,54.236 h1.02
  text "Layer 1 - Top Layer - Layer 4 - Bottom Layer" at 207.413,54.236 h1.02
  text "305 Total" at 152.401,51.696 h1.02
  text "Slot definitions :" at 143.727,49.173 h1.02
  text "Routed Path Length" at 161.308,49.173 h1.02
  text "= Calculated from tool start centre position to tool end centre position." at 180.075,49.173 h1.02
  text "Hole Length" at 161.308,47.412 h1.02
  text "= Routed Path Length + Tool Size = Slot length as defined in the PCB layout" at 173.135,47.412 h1.02
  text ".Layer_Name" at -13.844,-39.756 h1.52
M17 Embedded Cavity:
  text ".Layer_Name" at -13.844,-39.756 h1.52
M18 Embedded Assembly:
  text ".Layer_Name" at -13.844,-39.756 h1.52
M19 Embedded Keepout:
  text ".Layer_Name" at -13.844,-39.756 h1.52

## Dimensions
110.3,41.25 to 105.8,40.5 on M2 Board Dimensions
0,-16.35 to 25.4,-16.35 on M2 Board Dimensions
0,0 to 0,40.5 on M2 Board Dimensions
105.8,40.5 to 0,40.5 on M2 Board Dimensions
0,0 to 40.75,20.25 on M2 Board Dimensions
41.65,14.25 to 41.65,26.25 on M2 Board Dimensions
0,40.5 to 40.4,19.95 on M2 Board Dimensions
38.9,25.9 to 41.9,25.9 on M2 Board Dimensions
39.9,15.25 to 35.775,11.825 on M2 Board Dimensions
